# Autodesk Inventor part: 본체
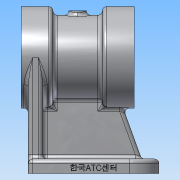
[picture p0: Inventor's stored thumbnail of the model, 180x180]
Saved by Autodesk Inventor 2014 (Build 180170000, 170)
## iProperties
Created: 2020-06
Part Number: 본체
Material: 알루미늄 6061
Document SubType Name: Modeling
Designer: NET
Density: 2.71 g/cm^3
Appearance: 알루미늄 - 평지
Mass: 727.735 g
Surface Area: 642.521 cm^2
Volume: 268.537 cm^3
Author: NET
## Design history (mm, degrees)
sketch "스케치1"
  geometry: L1 (0, 0)-(78, 0); L2 (0, 0)-(0, 35); L3 (0, 35)-(22, 35); L4 (22, 35)-(22, 29); L5 (22, 29)-(56, 29); L6 (56, 29)-(56, 35); L7 (56, 35)-(78, 35); L8 (78, 35)-(78, 0)
  constraints: 16 end point, 4 perpendicular, 2 horizontal, 2 parallel
  dimensions: "d0" = 70 diameter of L3 L1; "d1" = 78 distance between parallel lines of L8 L2; "d2" = 22 distance between parallel lines of L2 L4; "d3" = 22 distance between parallel lines of L8 L6; "d4" = 70 diameter of L7 L1; "d5" = 58 diameter of L5 L1
revolve "회전1" sketch "스케치1" stored, may be unused: angle "d6" = 90 deg
node "작업 평면2"
sketch "스케치5"
  geometry: L1 (-49, -70)-(49, -70); L2 (49, -70)-(49, -80); L3 (49, -80)-(-49, -80); L4 (-49, -80)-(-49, -70); L5 (0, 0)-(0, -52.1)
  constraints: 10 end point, 3 parallel, 1 horizontal, 1 perpendicular, 1 other
  dimensions: "d26" = 10 distance between parallel lines of L1 L3; "d27" = 98 distance between parallel lines of L2 L4; "d28" = 80 distance from line of L3 L5.start
extrude "돌출2" join sketch "스케치5" distance "d29" = 90; taper "d30" = 0 deg
sketch "스케치6"
  geometry: L1 (-49, -70)-(49, -70) reference; L2 (49, -70)-(49, -80) reference; L3 (-35, 0)-(-35, -70); L4 (35, 0)-(35, -70); A1 r 35 centre (0, 0) between (-35, 0) and (35, 0) reference; 1 further point
  constraints: 4 end point, 2 point on circle, 2 point on line, 2 tangent, 1 parallel, 1 perpendicular
extrude "돌출3" join sketch "스케치6" distance "d31" = 10; taper "d32" = 0 deg
sketch "스케치7"
  geometry: L1 (5, -70)-(5, 0) reference; L2 (5, -70)-(95, -70) reference; L3 (56, -35)-(78, -35) reference; L4 (83, -70)-(70.261, -35); L5 (95, -80)-(95, -70) reference; L6 (22, -29)-(56, -29) reference; L7 (70.261, -35)-(66.105, -23.582); L8 (66.105, -23.582)-(5, -23.582); L9 (5, 0)-(5, -35) reference; 1 further point
  constraints: 6 end point, 3 point on line, 1 collinear, 1 parallel
  dimensions: "d33" = 70 deg angle of L2 L4; "d34" = 12 distance from line of L5 L4.start; "d35" = 5.41817 distance between parallel lines of L6 L8
extrude "돌출4" join sketch "스케치7" stored distance "d36" = 10; taper "d37" = 0 deg
sketch "스케치8"
  geometry: L1 (0, 0)-(78, 0); L2 (78, -35)-(78, 35) reference; L3 (0, 23.5)-(18, 23.5); L4 (18, 23.5)-(18, 20); L5 (18, 20)-(24, 20); L6 (24, 20)-(24, 23); L7 (24, 23)-(54, 23); L8 (22, -28.566)-(22, 29) reference; L9 (54, 23)-(54, 20); L10 (54, 20)-(60, 20); L11 (60, 20)-(60, 23.5); L12 (60, 23.5)-(78, 23.5); L13 (0, -35)-(0, 35) reference
  constraints: 20 end point, 5 perpendicular, 3 parallel, 2 point on line, 1 midpoint, 1 vertical
  dimensions: "d38" = 47 diameter of L3 L1; "d39" = 40 diameter of L5 L1; "d40" = 46 diameter of L7 L1; "d41" = 18 distance between parallel lines of L13 L4; "d42" = 6 distance between parallel lines of L6 L4; "d43" = 30 distance between parallel lines of L6 L9; "d44" = 40 diameter of L10 L1; "d45" = 47 diameter of L12 L1; "d46" = 18 distance between parallel lines of L2 L11
revolve "회전2" sketch "스케치8" stored, may be unused: angle "d47" = 90 deg
sketch "스케치9"
  geometry: C1 r 23.5 at (0, 0) reference; C2 r 35 at (0, 0) reference; A1 r 28.5 centre (0, 0) between (0, 28.5) and (28.5, 0); 2 further points
  constraints: 4 point on circle, 2 horizontal alignment, 2 vertical alignment, 1 centre point, 1 coincident
  dimensions: "d48" = 57 diameter of A1
hole "구멍1" sketch "스케치9" at (0, 28.5), (28.5, 0), (0, -28.5), (-28.5, 0) diameter "d49" = 3.242; stored, may be unused: countersink angle "d53" = 90 deg, drill point angle "d55" = 118 deg; dims "d50" = 10, "d51" = 4, "d52" = 2, "d54" = 12
node "작업 평면4"
node "작업 평면5"
sketch "스케치10"
  geometry: L1 (35, -39)-(-35, -39) reference; C1 r 6 at (0, 0); 1 further point
  constraints: 1 centre point, 1 vertical alignment
  dimensions: "d57" = 12 diameter of C1; "d58" = 39 distance from line of L1 C1.centre
extrude "돌출5" join sketch "스케치10" distance "d59" = 3; taper "d60" = 0 deg; dims "d61" = 1.5, "d62" = 0
hole "구멍2" diameter "d65" = 5.188; stored, may be unused: countersink angle "d69" = 90 deg, drill point angle "d71" = 0 deg; dims "d63" = 10, "d64" = 10, "d66" = 10, "d67" = 4, "d68" = 2, "d70" = 20
sketch "스케치11"
  geometry: L1 (98, -90)-(0, -90) reference; 5 further points
  constraints: 2 horizontal alignment, 2 vertical alignment
  dimensions: "d72" = 36 distance of point (20, -20) point (20, -56); "d73" = 58 distance of point (78, -20) point (20, -20); "d74" = 29 horizontal distance of point (20, -56) point (49, -95); "d75" = 70 distance from line of point (20, -20) L1
hole "구멍3" sketch "스케치11" at (20, -56), (20, -20), (78, -56), (78, -20) diameter "d76" = 9; stored, may be unused: countersink angle "d80" = 90 deg, drill point angle "d82" = 0 deg; dims "d77" = 10, "d78" = 4, "d79" = 2, "d81" = 20
sketch "스케치12"
  geometry: L1 (0, 0)-(10, 0) reference; L2 (10, 0)-(10, 90) reference; 2 further points
  constraints: 1 other
  dimensions: "d83" = 4 distance from line of L2 point (6, 45); "d84" = 45 distance from line of point (6, 45) L1
extrude "돌출6" join sketch "스케치12" distance "d85" = 0.5; taper "d86" = 0 deg
fillet "모깎기1" dims "d87" = 0.3
sketch "스케치13"
  geometry: L1 (98, -90)-(98, 0) reference; L2 (0, 0)-(98, 0) reference; L3 (0, -90)-(0, 0) reference; L4 (98, 0)-(0, 0) reference; C1 r 4.5 at (20, -20) reference; C2 r 4.5 at (78, -20) reference; A1 r 20 centre (20, -20) between (20, 0) and (0, -20); A2 r 20 centre (78, -20) between (98, -20) and (78, 0); 1 further point
  constraints: 4 point on circle, 4 point on line, 2 centre point, 2 coincident, 2 tangent
extrude "돌출7" cut sketch "스케치13" stored distance "d88" = 0.5; taper "d89" = 0 deg
fillet "모깎기2" dims "d90" = 3
fillet "모깎기3" dims "d91" = 3
fillet "모깎기4" dims "d92" = 3
fillet "모깎기5" dims "d93" = 3
fillet "모깎기6" dims "d94" = 3
fillet "모깎기7" dims "d95" = 3
chamfer "모따기1" distance "d96" = 1; stored, may be unused: second distance "d97" = 2, angle "d98" = 45 deg
chamfer "모따기2" distance "d99" = 1; stored, may be unused: second distance "d100" = 2, angle "d101" = 45 deg
fillet "모깎기8" dims "d102" = 3
fillet "모깎기9" dims "d105" = 3
sketch "스케치14"
  geometry: L1 (0, -76.178)-(58.375, -76.178); L2 (58.375, -76.178)-(58.375, 56.048); L3 (58.375, 56.048)-(0, 56.048); L4 (0, 56.048)-(0, -76.178); C1 r 1.621 at (28.5, 0) reference
  constraints: 8 end point, 2 parallel, 1 horizontal, 1 perpendicular
extrude "돌출8" cut sketch "스케치14" stored distance "d103" = 0; taper "d104" = 0 deg
node "솔리드1"
mirror "대칭1"
other parameters: "d25" = -5, "d56" = -39
